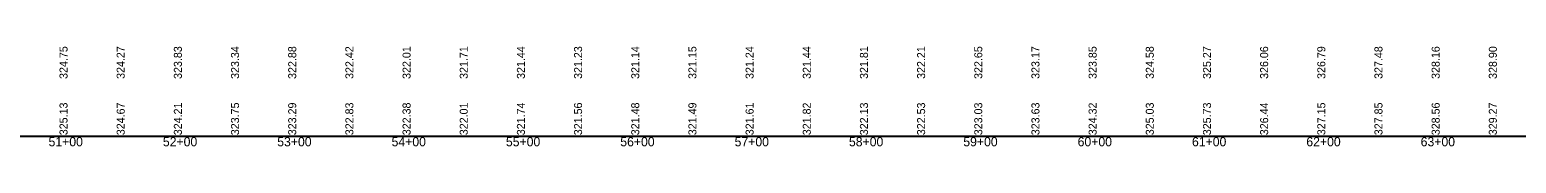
# Model space of a CAD drawing. Extents: x 1876258 to 1926563, y 729739 to 834437.
# Drawn here: x 1883429 to 1884729, y 830495 to 830583 of the extents above; entities that cross this region are included whole.
import ezdxf

# ---------------------------------------------------------------- set-up
doc = ezdxf.new("R2010")
doc.units = 0
for name, color, linetype in [('RD_EX_RailRoad', 7, 'Continuous'), ('RD_PD_ALT3_CL', 7, 'Continuous'), ('RD_PD_Final_Cl', 7, 'Continuous')]:
    doc.layers.add(name, color=color, linetype=linetype)

msp = doc.modelspace()

# ---------------------------------------------------------------- linework, layer by layer
at = {"layer": 'RD_PD_Final_Cl'}
msp.add_line((1878363.1, 830504.3), (1926563.1, 830504.3), dxfattribs=at)

# ---------------------------------------------------------------- texts
at = {"layer": 'RD_EX_RailRoad'}
for s, p in [('324.75', (1883462.1, 830554.3)), ('324.27', (1883512.1, 830554.3)), ('323.83', (1883562.1, 830554.3)), ('323.34', (1883612.1, 830554.3)), ('322.88', (1883662.1, 830554.3)), ('322.42', (1883712.1, 830554.3)), ('322.01', (1883762.1, 830554.3)), ('321.71', (1883812.1, 830554.3)), ('321.44', (1883862.1, 830554.3)), ('321.23', (1883912.1, 830554.3)), ('321.14', (1883962.1, 830554.3)), ('321.15', (1884012.1, 830554.3)), ('321.24', (1884062.1, 830554.3)), ('321.44', (1884112.1, 830554.3)), ('321.81', (1884162.1, 830554.3)), ('322.21', (1884212.1, 830554.3)), ('322.65', (1884262.1, 830554.3)), ('323.17', (1884312.1, 830554.3)), ('323.85', (1884362.1, 830554.3)), ('324.58', (1884412.1, 830554.3)), ('325.27', (1884462.1, 830554.3)), ('326.06', (1884512.1, 830554.3)), ('326.79', (1884562.1, 830554.3)), ('327.48', (1884612.1, 830554.3)), ('328.16', (1884662.1, 830554.3)), ('328.90', (1884712.1, 830554.3)), ('325.13', (1883462.1, 830505)), ('324.67', (1883512.1, 830505)), ('324.21', (1883562.1, 830505)), ('323.75', (1883612.1, 830505)), ('323.29', (1883662.1, 830505)), ('322.83', (1883712.1, 830505)), ('322.38', (1883762.1, 830505)), ('322.01', (1883812.1, 830505)), ('321.74', (1883862.1, 830505)), ('321.56', (1883912.1, 830505)), ('321.48', (1883962.1, 830505)), ('321.49', (1884012.1, 830505)), ('321.61', (1884062.1, 830505)), ('321.82', (1884112.1, 830505)), ('322.13', (1884162.1, 830505)), ('322.53', (1884212.1, 830505)), ('323.03', (1884262.1, 830505)), ('323.63', (1884312.1, 830505)), ('324.32', (1884362.1, 830505)), ('325.03', (1884412.1, 830505)), ('325.73', (1884462.1, 830505)), ('326.44', (1884512.1, 830505)), ('327.15', (1884562.1, 830505)), ('327.85', (1884612.1, 830505)), ('328.56', (1884662.1, 830505)), ('329.27', (1884712.1, 830505))]:
    msp.add_text(s, height=7, rotation=90, dxfattribs=at).set_placement(p)
at = {"layer": 'RD_PD_ALT3_CL'}
for s, p in [('51+00', (1883445.5, 830495.3)), ('51+00', (1883445.5, 830495.3)), ('52+00', (1883545.5, 830495.3)), ('52+00', (1883545.5, 830495.3)), ('53+00', (1883645.5, 830495.3)), ('53+00', (1883645.5, 830495.3)), ('54+00', (1883745.5, 830495.3)), ('54+00', (1883745.5, 830495.3)), ('55+00', (1883845.5, 830495.3)), ('55+00', (1883845.5, 830495.3)), ('56+00', (1883945.5, 830495.3)), ('56+00', (1883945.5, 830495.3)), ('57+00', (1884045.5, 830495.3)), ('57+00', (1884045.5, 830495.3)), ('58+00', (1884145.5, 830495.3)), ('58+00', (1884145.5, 830495.3)), ('59+00', (1884245.5, 830495.3)), ('59+00', (1884245.5, 830495.3)), ('60+00', (1884345.5, 830495.3)), ('60+00', (1884345.5, 830495.3)), ('61+00', (1884445.5, 830495.3)), ('61+00', (1884445.5, 830495.3)), ('62+00', (1884545.5, 830495.3)), ('62+00', (1884545.5, 830495.3)), ('63+00', (1884645.5, 830495.3)), ('63+00', (1884645.5, 830495.3))]:
    msp.add_text(s, height=8, dxfattribs=at).set_placement(p)

doc.saveas('drawing.dxf')
